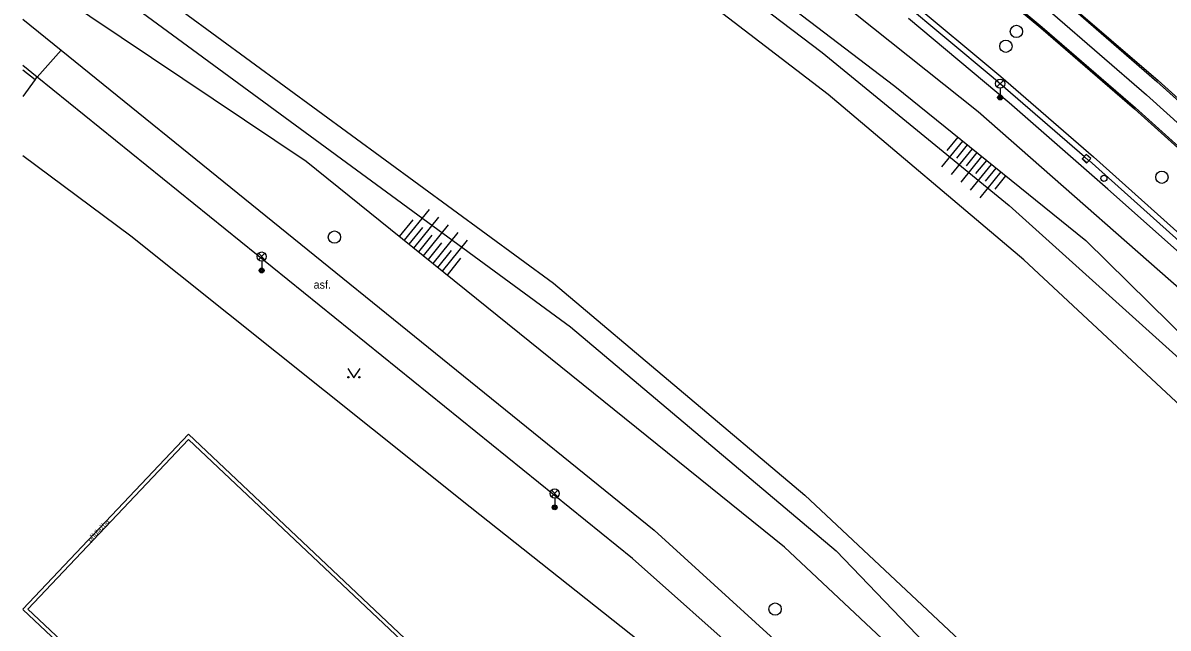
# Model space of a CAD drawing. Extents: x -598932 to -598196, y -1162207 to -1161504.
# Drawn here: x -598932 to -598839, y -1161792.6 to -1161743.4 of the extents above; entities that cross this region are included whole.
import ezdxf

# ---------------------------------------------------------------- set-up
doc = ezdxf.new("R2010")
doc.units = 0
for name, color, linetype in [('Level 27', 7, 'Continuous'), ('Level 28', 7, 'Continuous'), ('Level 33', 7, 'Continuous'), ('Level 36', 7, 'Continuous'), ('specificka linie pasportu komunikaci', 7, 'Continuous'), ('TM - CD - osa koleji', 7, 'Continuous'), ('TM - chodniky - VP', 7, 'Continuous'), ('TM - hladina vodniho toku_ bazenu_ nadrze', 7, 'Continuous'), ('TM - horni hrana svahu', 7, 'Continuous'), ('TM - komunikace - VP', 7, 'Continuous'), ('TM - letecke snimky - pomocna linie', 7, 'Continuous'), ('TM - plot dreveny_ kovovy - VP', 7, 'Continuous'), ('TM - popis povrchu', 7, 'Continuous'), ('TM - rozhrani mezi zpev. plochami mezi sebou - VP', 7, 'Continuous'), ('TM - rozhrani ploch obecne - VP', 7, 'Continuous'), ('TM - srafovani', 7, 'Continuous'), ('TM - svodidlo jednostranne - VP', 7, 'Continuous'), ('TM - zabradli - VP', 7, 'Continuous')]:
    doc.layers.add(name, color=color, linetype=linetype)

msp = doc.modelspace()

# ---------------------------------------------------------------- linework, layer by layer
at = {"layer": 'Level 27'}
msp.add_line((-598845.817, -1161754.254), (-598845.443, -1161754.586), dxfattribs=at)
msp.add_lwpolyline([(-598845.983, -1161754.44), (-598845.61, -1161754.773), (-598845.277, -1161754.4), (-598845.65, -1161754.067)], close=True, dxfattribs=at)
for centre in [(-598851.32, -1161744.08), (-598852.17, -1161745.29), (-598839.5, -1161755.93), (-598906.71, -1161760.79), (-598870.92, -1161791.01)]:
    msp.add_circle(centre, 0.5, dxfattribs=at)
at = {"layer": 'Level 28'}
msp.add_circle((-598844.21, -1161756.02), 0.25, dxfattribs=at)
at = {"layer": 'Level 33'}
for p, q in [((-598852.905, -1161748.59), (-598852.375, -1161748.06)), ((-598852.905, -1161748.06), (-598852.375, -1161748.59)), ((-598852.64, -1161748.7), (-598852.64, -1161749.45)), ((-598912.885, -1161762.64), (-598912.355, -1161762.11)), ((-598912.885, -1161762.11), (-598912.355, -1161762.64)), ((-598912.62, -1161762.75), (-598912.62, -1161763.5)), ((-598889.085, -1161781.89), (-598888.555, -1161781.36)), ((-598889.085, -1161781.36), (-598888.555, -1161781.89)), ((-598888.82, -1161782), (-598888.82, -1161782.75))]:
    msp.add_line(p, q, dxfattribs=at)
for centre, radius in [((-598852.64, -1161748.325), 0.375), ((-598852.64, -1161749.45), 0.2), ((-598852.64, -1161749.45), 0.145), ((-598852.64, -1161749.45), 0.0876), ((-598912.62, -1161762.375), 0.375), ((-598912.62, -1161763.5), 0.2), ((-598912.62, -1161763.5), 0.145), ((-598912.62, -1161763.5), 0.0876), ((-598888.82, -1161781.625), 0.375), ((-598888.82, -1161782.75), 0.2), ((-598888.82, -1161782.75), 0.145), ((-598888.82, -1161782.75), 0.0876)]:
    msp.add_circle(centre, radius, dxfattribs=at)
at = {"layer": 'Level 36'}
msp.add_lwpolyline([(-598905.63, -1161771.48), (-598905.13, -1161772.23), (-598904.63, -1161771.48)], dxfattribs=at)
for centre in [(-598905.58, -1161772.18), (-598904.681, -1161772.18)]:
    msp.add_circle(centre, 0.05, dxfattribs=at)
at = {"layer": 'specificka linie pasportu komunikaci'}
msp.add_lwpolyline([(-598931.02, -1161748), (-598930.851, -1161747.802), (-598928.9, -1161745.6)], dxfattribs=at)
at = {"layer": 'TM - CD - osa koleji'}
for points in [[(-598871.95, -1161723.62), (-598863.99, -1161729.82), (-598856.14, -1161736.16), (-598848.39, -1161742.63), (-598840.76, -1161749.23)], [(-598823.67, -1161764.63), (-598840.76, -1161749.23)]]:
    msp.add_lwpolyline(points, dxfattribs=at)
at = {"layer": 'TM - chodniky - VP'}
for points in [[(-598932.017, -1161743.075), (-598928.9, -1161745.6), (-598880.74, -1161784.6)], [(-598882.49, -1161786.91), (-598930.851, -1161747.802), (-598932.017, -1161746.859)], [(-598880.74, -1161784.6), (-598866.42, -1161797.65), (-598860.43, -1161803.84), (-598803.26, -1161864)], [(-598894.92, -1161816.68), (-598896, -1161817.83), (-598888.18, -1161825.78), (-598878.25, -1161821.22), (-598862.62, -1161806.01), (-598865.42, -1161803.14), (-598872.95, -1161795.42), (-598882.49, -1161786.91)]]:
    msp.add_lwpolyline(points, dxfattribs=at)
at = {"layer": 'TM - hladina vodniho toku_ bazenu_ nadrze'}
for points in [[(-598720.27, -1161904.76), (-598749.26, -1161871.38), (-598790.83, -1161824.98), (-598815.91, -1161796.95), (-598834.93, -1161777.35), (-598836.37, -1161776.01), (-598850.71, -1161762.63), (-598866.62, -1161749.21), (-598892.99, -1161728.98)], [(-598921.73, -1161740.47), (-598888.91, -1161764.54), (-598868.49, -1161781.76), (-598847.28, -1161801.66)]]:
    msp.add_lwpolyline(points, dxfattribs=at)
at = {"layer": 'TM - horni hrana svahu'}
for points in [[(-598932.017, -1161697.604), (-598929.76, -1161698.95), (-598888.91, -1161727.38), (-598861.19, -1161748.52), (-598845.68, -1161761.08), (-598825.16, -1161781.28), (-598808.06, -1161799.42), (-598788.14, -1161822.37), (-598765.72, -1161848.31), (-598730.99, -1161888.48), (-598729.85, -1161889.88)], [(-598737.74, -1161926.39), (-598791.69, -1161867.26), (-598813.1, -1161843.8), (-598846.83, -1161807.87), (-598870.15, -1161785.99), (-598909.01, -1161754.64), (-598931.6, -1161739.49), (-598932.017, -1161739.209)]]:
    msp.add_lwpolyline(points, dxfattribs=at)
at = {"layer": 'TM - komunikace - VP'}
for points in [[(-598876.07, -1161729.35), (-598868.35, -1161735.38), (-598860.72, -1161741.54), (-598853.2, -1161747.83), (-598845.79, -1161754.24)], [(-598845.95, -1161754.45), (-598845.79, -1161754.24)], [(-598845.59, -1161754.76), (-598845.95, -1161754.45)], [(-598845.59, -1161754.76), (-598845.41, -1161754.57), (-598828.96, -1161769.3), (-598822.48, -1161775.21), (-598822.95, -1161775.76), (-598822.6, -1161776.07), (-598822.11, -1161775.55), (-598813.72, -1161783.25), (-598807.19, -1161789.23)]]:
    msp.add_lwpolyline(points, dxfattribs=at)
at = {"layer": 'TM - letecke snimky - pomocna linie'}
for points in [[(-598889.27, -1161728.96), (-598867.09, -1161745.78), (-598851.9, -1161758.23), (-598837.29, -1161771.39), (-598832, -1161776.77)], [(-598932.017, -1161736.019), (-598925.65, -1161740.07), (-598887.55, -1161768.09), (-598865.96, -1161786.27), (-598821.99, -1161832.07), (-598791.69, -1161867.26)]]:
    msp.add_lwpolyline(points, dxfattribs=at)
at = {"layer": 'TM - plot dreveny_ kovovy - VP'}
for points in [[(-598932.017, -1161747.196), (-598931.02, -1161748), (-598932.017, -1161749.361)], [(-598932.017, -1161754.175), (-598923.24, -1161760.69), (-598895.69, -1161782.7)], [(-598918.56, -1161777.23), (-598931.61, -1161791.02)], [(-598891.67, -1161802.61), (-598918.56, -1161777.23)], [(-598895.69, -1161782.7), (-598867.5, -1161805.04), (-598887.12, -1161824.8)], [(-598931.61, -1161791.02), (-598904.66, -1161816.41)]]:
    msp.add_lwpolyline(points, dxfattribs=at)
at = {"layer": 'TM - rozhrani mezi zpev. plochami mezi sebou - VP'}
for points in [[(-598871.05, -1161722.54), (-598863.1, -1161728.74), (-598855.26, -1161735.07), (-598847.53, -1161741.54), (-598839.9, -1161748.14)], [(-598870.98, -1161722.45), (-598863.02, -1161728.66), (-598855.17, -1161735), (-598847.43, -1161741.48), (-598839.8, -1161748.08)], [(-598875.77, -1161728.99), (-598867.93, -1161735.11), (-598860.19, -1161741.37), (-598852.57, -1161747.75), (-598845.05, -1161754.27)], [(-598864.85, -1161731.07), (-598857.04, -1161737.37), (-598849.33, -1161743.8), (-598841.73, -1161750.36)], [(-598864.77, -1161730.99), (-598856.95, -1161737.3), (-598849.23, -1161743.73), (-598841.63, -1161750.3)], [(-598839.9, -1161748.14), (-598822.75, -1161763.56), (-598808.13, -1161777.02)], [(-598839.8, -1161748.08), (-598822.68, -1161763.48), (-598808.05, -1161776.94)], [(-598841.73, -1161750.36), (-598825.23, -1161765.21), (-598810.12, -1161779.09)], [(-598841.63, -1161750.3), (-598825.16, -1161765.13), (-598810.05, -1161779.01), (-598804.38, -1161784.26)], [(-598845.05, -1161754.27), (-598828.66, -1161768.95), (-598813.4, -1161782.91), (-598806.77, -1161788.96)]]:
    msp.add_lwpolyline(points, dxfattribs=at)
at = {"layer": 'TM - rozhrani ploch obecne - VP'}
for points in [[(-598932.017, -1161791.016), (-598918.57, -1161776.8)], [(-598918.57, -1161776.8), (-598891.25, -1161802.6)], [(-598904.65, -1161816.83), (-598932.017, -1161791.043)]]:
    msp.add_lwpolyline(points, dxfattribs=at)
at = {"layer": 'TM - srafovani'}
for points in [[(-598857.37, -1161755.08), (-598855.67, -1161752.99)], [(-598856.93, -1161753.75), (-598856.06, -1161752.67)], [(-598856.59, -1161755.71), (-598854.89, -1161753.62)], [(-598856.15, -1161754.37), (-598855.28, -1161753.3)], [(-598855.37, -1161755), (-598854.51, -1161753.93)], [(-598855.81, -1161756.34), (-598854.12, -1161754.25)], [(-598855.04, -1161756.97), (-598853.34, -1161754.88)], [(-598854.6, -1161755.63), (-598853.73, -1161754.56)], [(-598854.26, -1161757.6), (-598852.56, -1161755.5)], [(-598853.82, -1161756.26), (-598852.95, -1161755.19)], [(-598853.04, -1161756.89), (-598852.17, -1161755.82)], [(-598899.03, -1161758.54), (-598901.06, -1161761.05)], [(-598900.35, -1161759.38), (-598901.45, -1161760.74)], [(-598898.25, -1161759.16), (-598900.28, -1161761.68)], [(-598899.57, -1161760), (-598900.67, -1161761.37)], [(-598898.79, -1161760.63), (-598899.89, -1161761.99)], [(-598897.47, -1161759.79), (-598899.5, -1161762.31)], [(-598896.69, -1161760.42), (-598898.72, -1161762.94)], [(-598898.01, -1161761.26), (-598899.11, -1161762.62)], [(-598895.92, -1161761.05), (-598897.95, -1161763.56)], [(-598897.23, -1161761.89), (-598898.33, -1161763.25)], [(-598896.46, -1161762.51), (-598897.56, -1161763.88)]]:
    msp.add_lwpolyline(points, dxfattribs=at)
at = {"layer": 'TM - svodidlo jednostranne - VP'}
for points in [[(-598851.91, -1161749.88), (-598860.07, -1161743.02)], [(-598843.89, -1161756.89), (-598851.91, -1161749.88)], [(-598835.62, -1161764.24), (-598843.89, -1161756.89)]]:
    msp.add_lwpolyline(points, dxfattribs=at)
at = {"layer": 'TM - zabradli - VP'}
for points in [[(-598854.43, -1161750.62), (-598878.6, -1161731.32), (-598890.77, -1161722.52), (-598916.28, -1161704.63), (-598932.017, -1161694.547)], [(-598806.23, -1161798.45), (-598821.96, -1161780.88), (-598834.52, -1161768.12), (-598854.43, -1161750.62)]]:
    msp.add_lwpolyline(points, dxfattribs=at)

# ---------------------------------------------------------------- texts
at = {"layer": 'TM - popis povrchu'}
msp.add_text('asf.', height=0.65, dxfattribs=at).set_placement((-598908.4, -1161764.98))
msp.add_text('přídlažba', height=0.4, rotation=46.59163, dxfattribs=at).set_placement((-598926.52, -1161785.59))

doc.saveas('drawing.dxf')
